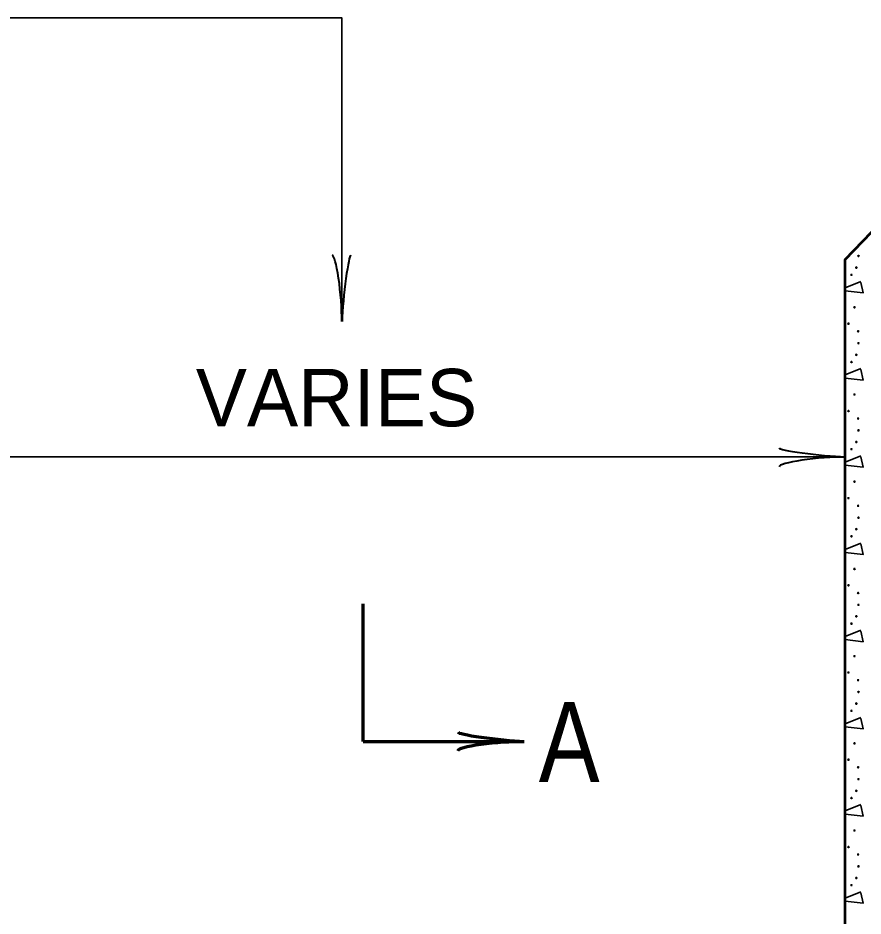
# Model space of a CAD drawing. Extents: x -105 to 751, y -65 to 479.
# Drawn here: x 59.56 to 103.75, y 325.31 to 372.28 of the extents above; entities that cross this region are included whole.
import ezdxf

# ---------------------------------------------------------------- set-up
doc = ezdxf.new("R2010")
doc.units = 0
doc.header["$LTSCALE"] = 1.2
doc.layers.add('1', color=7, linetype='Continuous', lineweight=35)

msp = doc.modelspace()

# ---------------------------------------------------------------- linework, layer by layer
at = {"layer": '1'}
for p, q in [((103.626, 358.5), (102.811, 358.171)), ((103.626, 353.94), (102.811, 353.611)), ((103.626, 349.38), (102.811, 349.05)), ((103.626, 344.82), (102.811, 344.49)), ((103.626, 340.26), (102.811, 339.93)), ((103.626, 335.7), (102.811, 335.37)), ((103.626, 331.14), (102.811, 330.81)), ((103.626, 326.58), (102.811, 326.25))]:
    msp.add_line(p, q, dxfattribs=at)
at = {"layer": '1', "lineweight": 70}
for q in [(77.611, 341.646), (86.011, 334.446)]:
    msp.add_line((77.611, 334.446), q, dxfattribs=at)
at = {"layer": '1'}
for points in [[(47.956, 372.279), (76.504, 372.279), (76.504, 356.414)], [(102.811, 358.008), (103.746, 357.9), (103.626, 358.452)], [(102.811, 353.448), (103.746, 353.34), (103.626, 353.892)], [(-4.811, 349.325), (51.451, 349.325), (102.811, 349.325)], [(102.811, 348.888), (103.746, 348.78), (103.626, 349.332)], [(102.811, 344.328), (103.746, 344.22), (103.626, 344.772)], [(102.811, 339.768), (103.746, 339.66), (103.626, 340.212)], [(102.811, 335.208), (103.746, 335.1), (103.626, 335.652)], [(102.811, 330.648), (103.746, 330.54), (103.626, 331.092)], [(102.811, 326.088), (103.746, 325.98), (103.626, 326.532)]]:
    msp.add_lwpolyline(points, dxfattribs=at)
at = {"layer": '1', "lineweight": 53}
msp.add_lwpolyline([(58.533, 316.446), (102.811, 316.446), (102.811, 359.646), (106.979, 363.962), (141.779, 363.962), (145.947, 359.646), (145.947, 281.046), (120.996, 281.046), (120.176, 278.791), (118.534, 283.301), (117.713, 281.046), (42.713, 281.046), (41.892, 278.791), (40.251, 283.301), (39.43, 281.046), (-6.77, 281.046), (-7.591, 278.791), (-9.232, 283.301), (-10.053, 281.046), (-27.453, 281.046), (-27.453, 285.944), (-29.708, 286.765), (-25.198, 288.406), (-27.453, 289.227)], dxfattribs=at)
at = {"layer": '1'}
for centre in [(103.509, 359.829), (103.143, 358.848), (103.398, 359.224), (103.302, 357.146), (102.984, 356.287), (103.493, 355.889), (103.509, 355.269), (103.398, 354.664), (103.143, 354.288), (103.302, 352.586), (102.984, 351.727), (103.493, 351.329), (103.509, 350.709), (103.398, 350.104), (103.143, 349.728), (103.302, 348.026), (102.984, 347.167), (103.493, 346.769), (103.509, 346.149), (103.143, 345.168), (103.398, 345.544), (103.302, 343.466), (102.984, 342.607), (103.493, 342.209), (103.509, 341.589), (103.398, 340.984), (103.143, 340.608), (103.302, 338.906), (102.984, 338.047), (103.493, 337.649), (103.509, 337.029), (103.398, 336.424), (103.143, 336.048), (103.302, 334.346), (102.984, 333.487), (103.493, 333.089), (103.509, 332.469), (103.398, 331.864), (103.143, 331.488), (103.302, 329.786), (102.984, 328.927), (103.493, 328.529), (103.509, 327.909), (103.143, 326.928), (103.398, 327.304)]:
    msp.add_circle(centre, 0.0318, dxfattribs=at)
at = {"layer": '1', "lineweight": 40}
for centre, major_axis, ratio, start_param, end_param in [((76.172, 357.724), (0.187, -2.143), 0.122415, 0.896353, 3.141593), ((76.757, 357.759), (-0.211, -2.108), 0.07063, 3.140715, 5.41811), ((101.466, 349.579), (2.108, -0.211), 0.07063, 3.140715, 5.41811), ((101.501, 348.993), (2.143, 0.187), 0.122415, 0.896353, 3.141593)]:
    msp.add_ellipse(centre, major_axis=major_axis, ratio=ratio, start_param=start_param, end_param=end_param, dxfattribs=at)
at = {"layer": '1', "lineweight": 70}
for centre, major_axis, ratio, start_param, end_param in [((84.68, 334.704), (2.105, -0.233), 0.07063, 3.140715, 5.41811), ((84.709, 334.118), (2.145, 0.165), 0.122415, 0.896353, 3.141593)]:
    msp.add_ellipse(centre, major_axis=major_axis, ratio=ratio, start_param=start_param, end_param=end_param, dxfattribs=at)

# ---------------------------------------------------------------- texts
at = {"layer": '1'}
msp.add_text('VARIES', height=3, dxfattribs=at).set_placement((68.861, 350.926))
at = {"layer": '1', "width": 0.85}
msp.add_text('A', height=4.2, dxfattribs=at).set_placement((86.792, 332.315))

doc.saveas('drawing.dxf')
